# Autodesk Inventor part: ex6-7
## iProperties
Shininess: 64.0
Length Units: 11272
Angle Units: 11279
Time Units: 11290
Mass Units: 11286
Length Display Precision: 3
Angle Display Precision: 2
Compacted: True
Part Number: ex6-7
Document SubType Name: Modeling
Created: 2002-11
Designer: Elise Moss
Density: 0.0
Volumn: 0.0
Area: 0.0
PropertySet Name: Model Information
Control State: 0
Master: False
Checked Out: False
Author: Elise Moss
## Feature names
1. Extrusion1
2. Extrusion2
